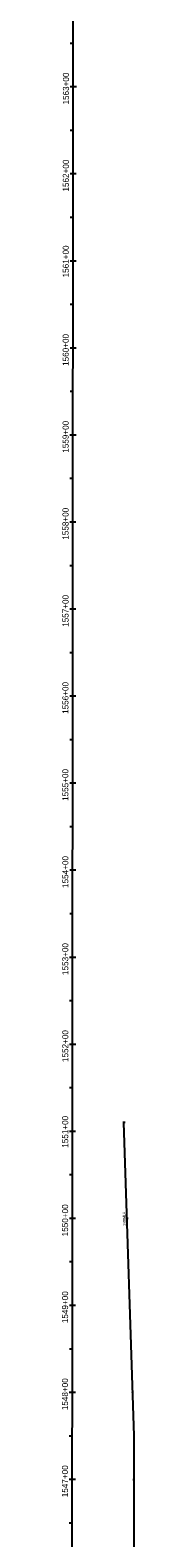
# Model space of a CAD drawing. Extents: x 596008 to 607538, y 326212 to 405053.
# Drawn here: x 603216 to 603299, y 378969 to 380701 of the extents above; entities that cross this region are included whole.
import ezdxf

# ---------------------------------------------------------------- set-up
doc = ezdxf.new("R2010")
doc.units = 0
for name, color, linetype in [('P_ALI_200', 7, 'Continuous'), ('P_ALI_200_Sta', 7, 'Continuous'), ('P_ALI_HLA', 7, 'Continuous'), ('P_ALI_HLA (1)', 7, 'Continuous'), ('P_ALI_Sta', 7, 'Continuous'), ('P_ALI_Tic', 7, 'Continuous')]:
    doc.layers.add(name, color=color, linetype=linetype)

msp = doc.modelspace()

# ---------------------------------------------------------------- linework, layer by layer
at = {"layer": 'P_ALI_200'}
for points in [[(603229, 380091.5), (603232.3, 384065)], [(603225.4, 374115.8), (603229, 380091.5)]]:
    msp.add_lwpolyline(points, dxfattribs=at)
at = {"layer": 'P_ALI_200_Sta'}
for points in [[(603229.5, 380686), (603226, 380686)], [(603229.5, 380636), (603226, 380636)], [(603229.5, 380636), (603229.5, 380636)], [(603233, 380636), (603229.5, 380636)], [(603229.4, 380586), (603225.9, 380586)], [(603229.4, 380536), (603225.9, 380536)], [(603229.4, 380536), (603229.4, 380536)], [(603232.9, 380536), (603229.4, 380536)], [(603229.3, 380486), (603225.8, 380486)], [(603229.3, 380436), (603225.8, 380436)], [(603229.3, 380436), (603229.3, 380436)], [(603232.8, 380436), (603229.3, 380436)], [(603229.3, 380386), (603225.8, 380386)], [(603229.2, 380336), (603225.7, 380336)], [(603229.2, 380336), (603229.2, 380336)], [(603232.7, 380336), (603229.2, 380336)], [(603229.2, 380286), (603225.7, 380286)], [(603229.1, 380236), (603225.6, 380236)], [(603229.1, 380236), (603229.1, 380236)], [(603232.6, 380236), (603229.1, 380236)], [(603229.1, 380186), (603225.6, 380186)], [(603229, 380136), (603225.5, 380136)], [(603229, 380136), (603229, 380136)], [(603232.5, 380136), (603229, 380136)], [(603229, 380086), (603225.5, 380086)], [(603229, 380036), (603225.5, 380036)], [(603229, 380036), (603229, 380036)], [(603232.5, 380036), (603229, 380036)], [(603228.9, 379986), (603225.4, 379986)], [(603228.9, 379936), (603225.4, 379936)], [(603228.9, 379936), (603228.9, 379936)], [(603232.4, 379936), (603228.9, 379936)], [(603228.9, 379886), (603225.4, 379886)], [(603228.9, 379836), (603225.4, 379836)], [(603228.9, 379836), (603228.9, 379836)], [(603232.4, 379836), (603228.9, 379836)], [(603228.8, 379786), (603225.3, 379786)], [(603228.8, 379736), (603225.3, 379736)], [(603228.8, 379736), (603228.8, 379736)], [(603232.3, 379736), (603228.8, 379736)], [(603228.8, 379686), (603225.3, 379686)], [(603228.7, 379636), (603225.2, 379636)], [(603228.7, 379636), (603228.7, 379636)], [(603232.2, 379636), (603228.7, 379636)], [(603228.7, 379586), (603225.2, 379586)], [(603228.7, 379536), (603225.2, 379536)], [(603228.7, 379536), (603228.7, 379536)], [(603232.2, 379536), (603228.7, 379536)], [(603228.6, 379486), (603225.1, 379486)], [(603228.6, 379436), (603225.1, 379436)], [(603228.6, 379436), (603228.6, 379436)], [(603232.1, 379436), (603228.6, 379436)], [(603228.6, 379386), (603225.1, 379386)], [(603228.6, 379336), (603225.1, 379336)], [(603228.6, 379336), (603228.6, 379336)], [(603232.1, 379336), (603228.6, 379336)], [(603228.5, 379286), (603225, 379286)], [(603228.5, 379236), (603225, 379236)], [(603228.5, 379236), (603228.5, 379236)], [(603232, 379236), (603228.5, 379236)], [(603228.5, 379186), (603225, 379186)], [(603228.4, 379136), (603224.9, 379136)], [(603228.4, 379136), (603228.4, 379136)], [(603231.9, 379136), (603228.4, 379136)], [(603228.4, 379086), (603224.9, 379086)], [(603228.4, 379036), (603224.9, 379036)], [(603228.4, 379036), (603228.4, 379036)], [(603231.9, 379036), (603228.4, 379036)], [(603228.3, 378986), (603224.8, 378986)]]:
    msp.add_lwpolyline(points, dxfattribs=at)
at = {"layer": 'P_ALI_HLA'}
for points in [[(603299.4, 379086.4), (603287.6, 379446.3)], [(603299.1, 378586.4), (603299.4, 379086.4)]]:
    msp.add_lwpolyline(points, dxfattribs=at)
at = {"layer": 'P_ALI_HLA (1)'}
for points in [[(603299.4, 379086.4), (603287.6, 379446.3)], [(603299.1, 378586.4), (603299.4, 379086.4)]]:
    msp.add_lwpolyline(points, dxfattribs=at)
at = {"layer": 'P_ALI_Sta'}
for points in [[(603287.6, 379446.3), (603286.2, 379446.2)], [(603287.6, 379446.3), (603286.2, 379446.2)], [(603289, 379446.3), (603287.6, 379446.3)], [(603289, 379446.3), (603287.6, 379446.3)], [(603291.2, 379335.8), (603289.8, 379335.7)], [(603291.2, 379335.8), (603289.8, 379335.7)], [(603292.6, 379335.8), (603291.2, 379335.8)], [(603292.6, 379335.8), (603291.2, 379335.8)]]:
    msp.add_lwpolyline(points, dxfattribs=at)
at = {"layer": 'P_ALI_Tic'}
for points in [[(603288, 379435.7), (603286.6, 379435.7)], [(603288, 379435.7), (603286.6, 379435.7)], [(603294.5, 379235.8), (603293.1, 379235.8)], [(603294.5, 379235.8), (603293.1, 379235.8)], [(603297.8, 379135.9), (603296.4, 379135.8)], [(603297.8, 379135.9), (603296.4, 379135.8)], [(603299.4, 379035.9), (603298, 379035.9)], [(603299.4, 379035.9), (603298, 379035.9)]]:
    msp.add_lwpolyline(points, dxfattribs=at)

# ---------------------------------------------------------------- texts
at = {"layer": 'P_ALI_200_Sta'}
for s, rotation, p in [('1563+00', 89.952, (603224.5, 380615.8)), ('1562+00', 89.952, (603224.4, 380515.8)), ('1561+00', 89.952, (603224.3, 380417.2)), ('1560+00', 89.952, (603224.2, 380315.5)), ('1559+00', 89.952, (603224.1, 380215.7)), ('1558+00', 89.952, (603224, 380115.8)), ('1557+00', 89.9657, (603224, 380015.7)), ('1556+00', 89.9657, (603223.9, 379915.7)), ('1555+00', 89.9657, (603223.8, 379815.7)), ('1554+00', 89.9657, (603223.8, 379715.7)), ('1553+00', 89.9657, (603223.7, 379615.7)), ('1552+00', 89.9657, (603223.7, 379515.7)), ('1551+00', 89.9657, (603223.6, 379417.2)), ('1550+00', 89.9657, (603223.5, 379315.5)), ('1549+00', 89.9657, (603223.5, 379215.7)), ('1548+00', 89.9657, (603223.4, 379115.7)), ('1547+00', 89.9657, (603223.4, 379015.7))]:
    msp.add_text(s, height=7, rotation=rotation, dxfattribs=at).set_placement(p)
at = {"layer": 'P_ALI_Sta'}
for s, height, p in [('1551HLA', 0.00000000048, (603285.6, 379446.2)), ('1551', 0.00000000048, (603285.6, 379446.2)), ('1550HLA', 2.8, (603289.5, 379327.5)), ('1550', 2.8, (603289.4, 379331.1))]:
    msp.add_text(s, height=height, rotation=91.8759, dxfattribs=at).set_placement(p)

doc.saveas('drawing.dxf')
